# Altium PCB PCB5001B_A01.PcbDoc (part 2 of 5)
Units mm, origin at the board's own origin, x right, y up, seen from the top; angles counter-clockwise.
Board outline 115 x 60 mm, 6 copper layers (Top Layer, GND Layer 2, Signal Layer 3, Signal Layer 4, VCC Layer 5, Bottom Layer), stack 1.555 mm thick; 370 components, 274 nets, 1305 pads, 1129 vias.
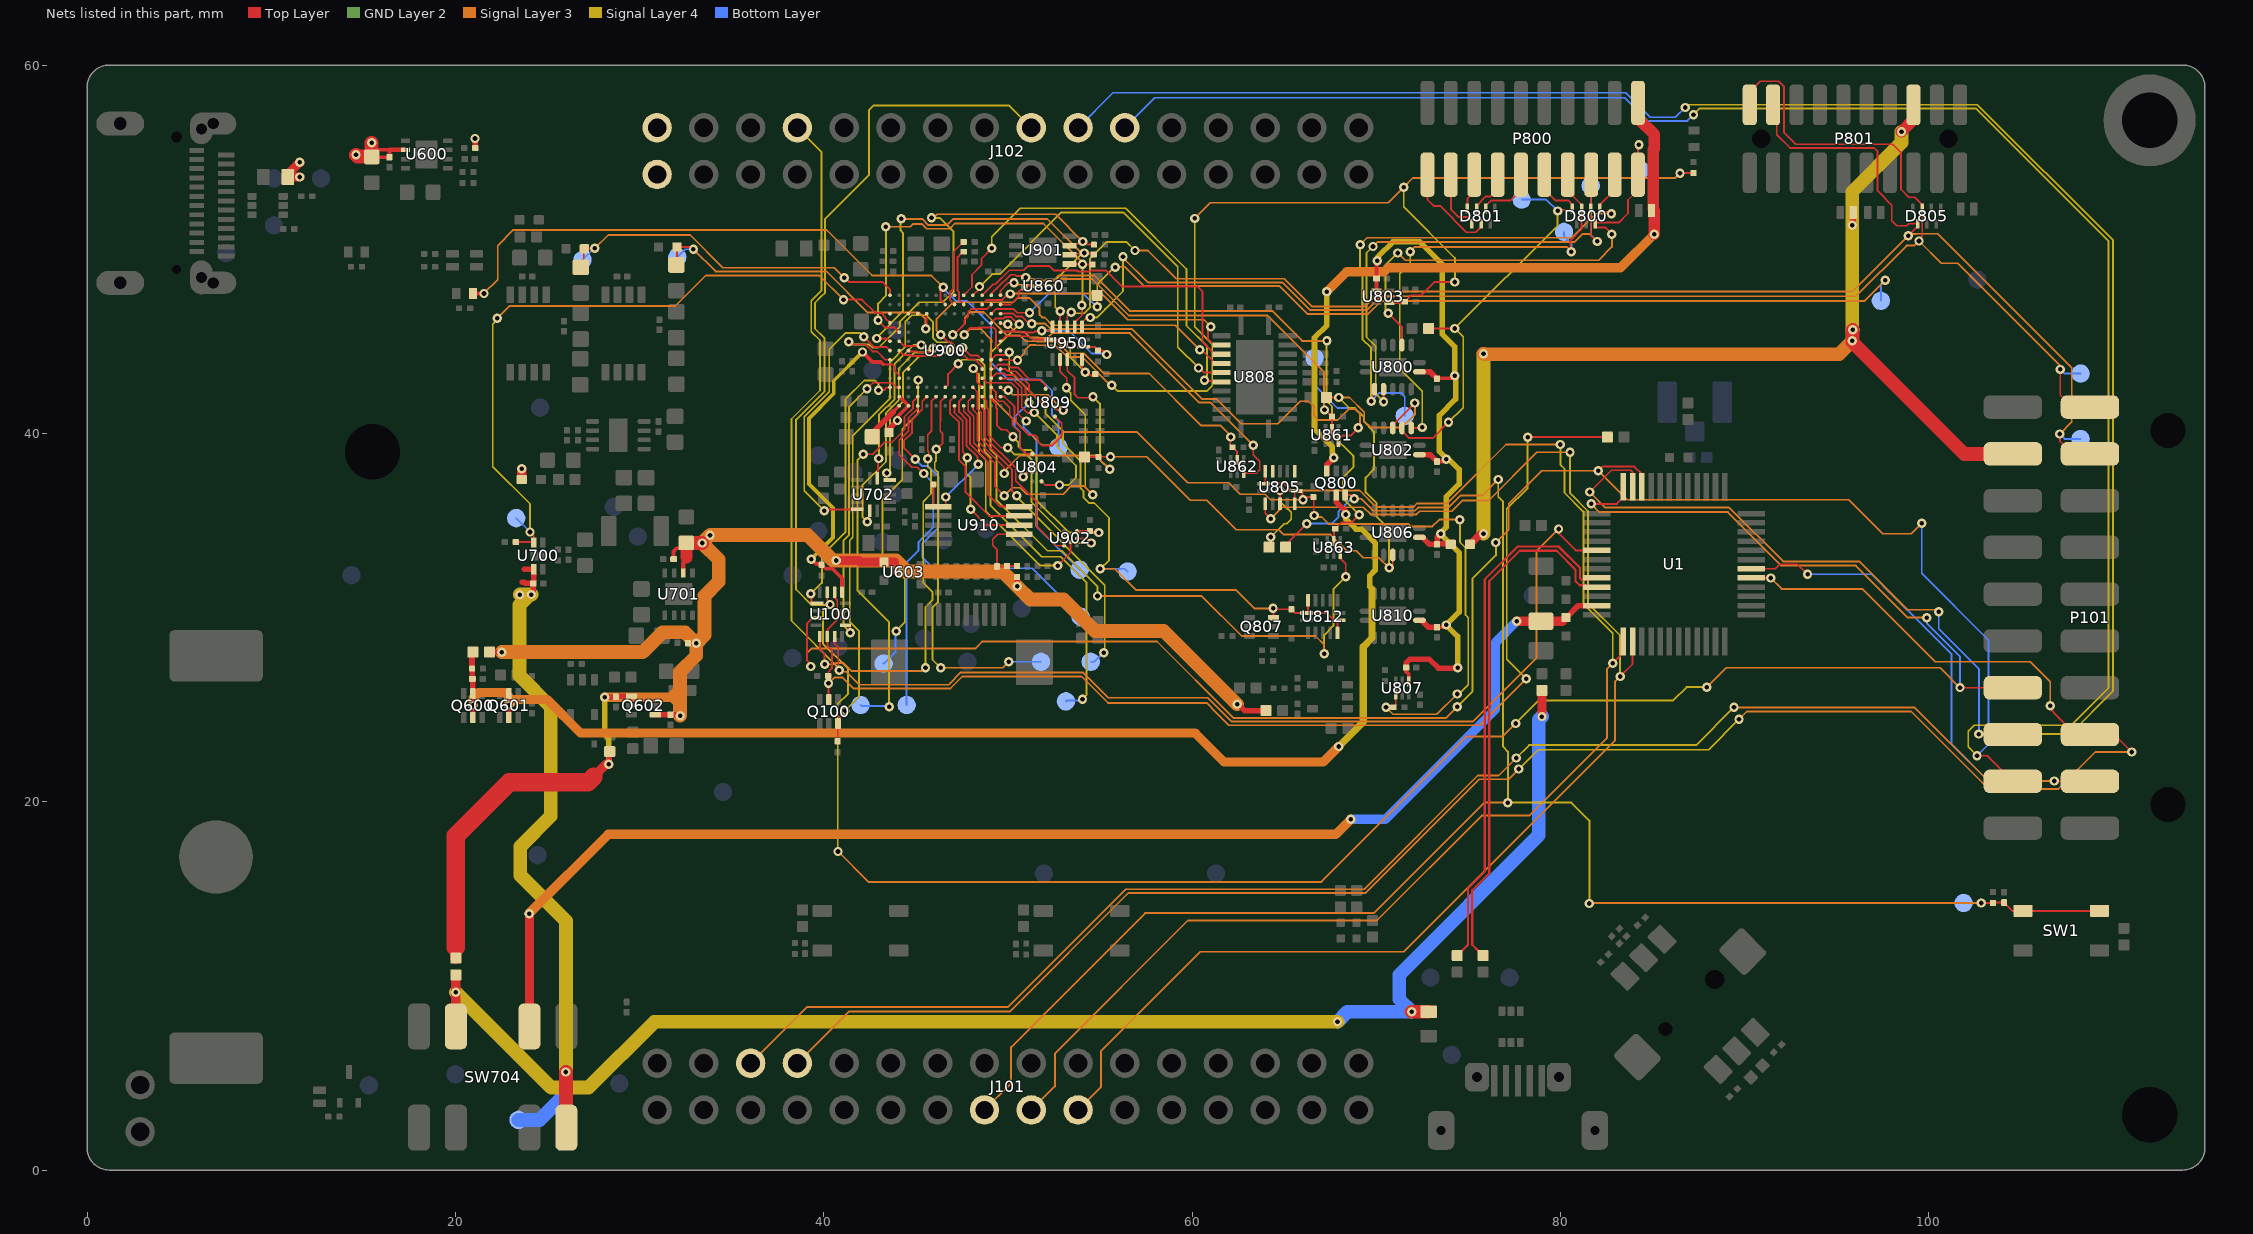
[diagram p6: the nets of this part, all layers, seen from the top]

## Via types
v1: diameter 0.508, hole 0.25, Top Layer to Bottom Layer, tented both sides, 1129 vias

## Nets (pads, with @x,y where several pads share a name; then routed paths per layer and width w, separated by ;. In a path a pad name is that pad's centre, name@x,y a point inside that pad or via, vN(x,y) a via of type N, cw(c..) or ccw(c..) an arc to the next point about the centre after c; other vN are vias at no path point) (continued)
5V: C600.1 C609.1 C611.1 C673.1 C674.1 C702.1 C703.1 C901.1 D806.1 J102.1 J102.2 L600.2 L700.1 L800.1 P101.18 P801.5 Q602.1 Q602.4 R600.2 R622.2 R633.2 R681.2 R690.2 R700.2 R793.2 U600.2 U603.A2 U603.B2 U701.2 U900.A11 U900.B12 | length 163.1
  Top Layer w0.2: C611.1@15.503,55.397 16.417,55.397 C600.1@16.417,55.001 15.726,55.001 C611.1@15.7,54.975 ; C702.1@31.845,33.231 31.845,33.595 32.011,33.761 32.311,33.761 C703.1@32.4,33.85 ; 32.375,32.975 32.475,33.075 ; R700.2@32.627,28.611 32.632,28.606 33.069,28.606 v1(33.075,28.6) ; 43.85,33.025 44.15,32.725 U603.B2@44.15,32.65 44.025,32.65 43.9,32.525 43.9,32.375 44.025,32.25 U603.A2@44.15,32.25 ; v1(44.002,40.702) 44.002,40.902 U900.A11@44.6,41.5 U900.B12@44.1,42
  Top Layer w0.25: 16.417,55.397 U600.2@17.282,55.397 ; U701.2@32.375,32.425 32.375,32.975
  Top Layer w0.3: v1(21.061,56.017) 21.072,56.007 21.072,55.507 R600.2@21.082,55.497 ; R622.2@21.85,28.125 v1(22.525,28.125) ; v1(28.1,25.675) 28.111,25.686 28.703,25.686 C674.1@28.713,25.697 ; v1(28.335,22.042) 28.357,22.065 28.357,22.699 R681.2@28.38,22.722 ; C674.1@28.713,25.697 28.713,25.715 28.723,25.725 Q602.1@29.55,25.725 ; Q602.4@30.85,24.725 C673.1@31.675,24.725 ; C673.1@31.675,24.721 31.685,24.711 32.105,24.711 32.145,24.671 v1(32.201,24.671) ; C901.1@43.55,40.05 43.55,40.25 v1(44.002,40.702) ; v1(50.5,31.7) R633.2@50.5,32.2 ; v1(62.447,25.294) 62.503,25.294 62.853,24.944 R690.2@64.021,24.944 ; v1(95.85,51.3) 95.9,51.35 D806.1@95.9,52
  Top Layer w0.4: L800.1@75.099,33.978 75.671,34.55 v1(75.825,34.55)
  Top Layer w0.5: L600.2@10.9,53.926 v1@11.549,53.926 ; L600.2@10.9,53.926 10.985,54.011 10.985,54.154 11.551,54.719 v1(11.551,54.722) ; L700.1@23.6,37.5 v1(23.6,38.075) ; v1(40.682,33.1) 41.919,33.1 41.994,33.025 C609.1@43.275,33.025 43.85,33.025
  Top Layer w0.508: 27.5,21.35 28.192,22.042 v1(28.335,22.042)
  Top Layer w0.635: R793.2@20.025,11.503 20.025,12.1 ; v1(98.525,56.375) 99.175,57.025 P801.5@99.175,57.841
  Top Layer w0.65: 32.55,33.25 C703.1@32.55,34.047
  Top Layer w0.75: v1(14.6,55.125) 14.686,55.039 15.44,55.039 C611.1@15.45,55.029 ; v1(15.45,55.775) C611.1@15.45,55.029 ; C611.1@15.465,55.014 C611.1@15.45,55.029 ; C703.1@32.55,34.047 32.547,34.05 v1(33.4,34.05) ; v1(95.875,45.625) 95.875,45.05 v1(95.85,45.025) 95.85,44.975 101.935,38.89 P101.18@104.57,38.89
  Top Layer w1: 20.025,12.1 20.025,18.15 22.925,21.05 27.2,21.05 27.5,21.35
  Signal Layer 3 w0.5: v1(28.1,25.675) 31.65,25.675 ; 32.075,26.15 32.075,26.1 31.65,25.675 ; 32.175,25.25 31.75,25.675 ; 32.201,25.675 31.75,25.675 ; 31.65,25.675 31.75,25.675
  Signal Layer 3 w0.75: v1(22.525,28.125) 30.175,28.125 31.25,29.2 32.475,29.2 v1(33.075,28.6) 33.086,28.6 33.525,29.039 33.525,31.175 34.3,31.95 34.3,33.15 v1(33.4,34.05) v1(33.825,34.475) 33.833,34.483 39.117,34.483 40.5,33.1 40.74,33.1 43.925,33.1 44.525,32.5 49.7,32.5 v1(50.5,31.7) 51.218,30.982 53.018,30.982 54.725,29.275 58.466,29.275 61.66,26.081 v1(62.447,25.294) ; v1(32.201,24.671) 32.201,25.675 32.201,27.051 33.075,27.925 v1@33.075,28.525 ; v1(75.825,44.325) 75.85,44.3 95.125,44.3 v1(95.85,45.025) 95.85,45.6 v1(95.875,45.625)
  Signal Layer 4 w0.3: v1(28.1,25.675) 28.1,23.65 28.335,23.415 v1(28.335,22.042)
  Signal Layer 4 w0.75: v1(75.825,34.55) v1(75.825,44.325) ; v1@95.85,45.625 v1(95.85,51.3) 95.85,53.125 98.525,55.8 v1(98.525,56.375)
  other v1: 11.55,53.925
5V_DH_SW: C803.1 C805.1 C809.1 C827.1 C869.1 C870.1 L800.2 U800.14 U802.14 U803.1 U806.14 U807.1 U810.14 | length 42.6
  Top Layer w0.2: C827.1@73.3,29.475 73.675,29.475 v1(73.8,29.6) ; C805.1@73.3,38.475 73.675,38.475 v1(73.8,38.6) ; C803.1@73.325,43 74.15,43 v1(74.275,43.125)
  Top Layer w0.203: U803.1@70.025,47.775 70.019,47.781 C869.1@70.019,48.403 70.019,49.344 v1(70.05,49.375) ; C870.1@71.625,27.284 71.625,27.075 71.763,26.937 U807.1@71.763,26.525
  Top Layer w0.3: C870.1@71.625,27.284 71.625,27.544 71.831,27.75 72.875,27.75 73.375,27.25 74.4,27.25 v1(74.425,27.275) ; U810.14@72.35,29.85 72.475,29.85 72.85,29.475 C827.1@73.3,29.475 ; U806.14@72.35,34.35 72.525,34.35 72.9,33.975 C809.1@73.3,33.975 73.31,33.985 73.31,34.371 73.49,34.551 v1(73.511,34.551) ; U802.14@72.35,38.85 72.925,38.85 C805.1@73.3,38.475 ; U800.14@72.35,43.35 72.925,43.35 C803.1@73.3,42.975 C803.1@73.325,43 ; C809.1@73.31,34 74.028,34 L800.2@74.049,33.978
  Signal Layer 4 w0.203: v1(70.05,49.375) 70.05,49.6 70.08,49.631 70.134,49.631
  Signal Layer 4 w0.3: 70.134,49.631 70.904,50.4 72.375,50.4 73.438,49.337 73.6,49.175 73.6,45.375 74.275,44.7 v1(74.275,43.125) ; v1(73.8,38.6) 73.8,38.656 73.432,39.024 73.432,40.982 74.318,41.868 v1@74.318,42.935 ; v1@73.875,38.675 74.5,38.05 74.5,37.25 73.8,36.55 73.8,34.897 73.511,34.607 73.511,34.514 74.5,33.525 74.5,30.3 v1(73.8,29.6) 74.425,28.975 v1(74.425,27.275)
5V_SENSE: C635.1 R633.1 R634.2 U910.7 | length 4.2
  Top Layer w0.1: R633.1@50.5,32.8 R634.2@49.95,32.8 49.925,32.775 C635.1@49.4,32.775 49.4,33.7 49.182,33.918 49.182,34.263 49.444,34.525 U910.7@50.625,34.525
5V_SW: C610.1 Q600.2 Q600.5 Q601.2 Q601.5 Q800.5 R622.1 R623.2 | length 70.5
  Top Layer w0.3: C610.1@20.925,26.675 20.925,27.2 R623.2@20.9,27.225 20.9,28.075 R622.1@20.95,28.125 ; Q600.2@20.95,24.575 v1(20.95,25.225) 20.95,25.25 Q600.5@20.95,25.875 C610.1@20.95,26.65 ; Q601.2@22.9,24.575 v1(22.9,25.25) Q601.5@22.9,25.875 ; Q800.5@67.825,36.65 67.825,36.275 68.35,35.75 v1(68.35,35.6)
  Signal Layer 3 w0.5: v1(20.95,25.225) 20.95,25.626 21.249,25.925 22.675,25.925 22.9,25.7 v1(22.9,25.25) 23.2,25.55 23.45,25.55 24.975,25.55 26.8,23.725 60.175,23.725 61.75,22.15 67.11,22.15 v1(67.96,23)
  Signal Layer 4 w0.3: v1(68.35,35.6) 68.35,35.35 68.9,34.8 69.2,34.8 69.95,34.05 69.95,32.575 69.643,32.268 69.643,31.682 69.775,31.55
  Signal Layer 4 w0.4: v1(67.96,23) 69.307,24.347 69.307,28.425 69.775,28.893 69.775,31.55
#RESET: R805.2 R809.1 R810.2 U802.4 U806.11 | length 39.3
  Top Layer w0.1: R810.2@54.15,38.725 R809.1@54.925,38.725 54.938,38.737 v1(55.575,38.737) ; R805.2@67.3,41.95 v1(67.975,41.95) ; v1(70.7,32.7) 70.9,32.9 U806.11@70.9,33.4 ; U802.4@70.9,40.3 70.9,40.45 v1(72.1,41.65)
  Signal Layer 3 w0.1: v1(55.575,38.737) 57.537,38.737 59.9,36.375 60.8,36.375 62.407,34.768 64.72,34.768 64.98,34.507 67.518,34.507 68.393,33.632 68.918,33.632 69.3,33.25 70.15,33.25 v1(70.7,32.7) ; v1(67.975,41.95) 68.55,41.95 69.35,41.15 69.35,40.675 69.7,40.325 71.4,40.325 72.1,41.025 v1(72.1,41.65)
  Signal Layer 4 w0.1: v1(67.975,41.95) 68.55,41.375 68.85,41.375 69.325,40.9 69.325,40.65 69.875,40.1 69.875,38.05 69.425,37.6 69.425,36.8 70.025,36.2 70.025,35.475 70.7,34.8 v1(70.7,32.7)
AEM_5V_#ENABLE: U900.L10
AEM_CALIBRATE0: U702.13 U900.G11 | length 13.7
  Top Layer w0.1: v1(42.368,35.213) 42.446,35.291 42.446,35.457 42.5,35.511 U702.13@42.5,35.79 ; U900.G11@44.6,44.5 44.65,44.45 45.099,44.45 45.14,44.409 45.709,44.409 v1(45.935,44.635)
  Signal Layer 4 w0.1: v1(42.368,35.213) 42.1,35.481 42.1,37.189 43.388,38.476 43.388,41.113 44.075,41.8 44.075,43.525 44.95,44.4 45.527,44.4 45.629,44.502 45.803,44.502 v1(45.935,44.635)
AEM_CALIBRATE1: U702.5 U900.G12 | length 12.1
  Top Layer w0.1: v1(43.425,37.85) 43.425,37.525 43.475,37.475 U702.5@43.585,37.475 ; U900.G12@44.1,44.5 44.35,44.25 44.704,44.25 44.752,44.202 46.327,44.202 v1(46.675,44.55)
  GND Layer 2 w0.1: v1(43.425,37.85) v1@43.483,37.908
  Signal Layer 4 w0.1: v1(43.425,37.85) 43.503,37.928 43.6,38.025 43.6,38.75 43.6,41.025 44.3,41.725 44.3,43.3 45.193,44.193 46.318,44.193 v1(46.675,44.55)
AEM_CALIBRATE2: U702.6 U900.H12 | length 9.8
  Top Layer w0.1: U702.6@42.9,37.56 42.947,37.607 42.947,38.592 v1(42.995,38.639) ; U900.H12@44.1,45 44.35,44.75 45.25,44.75 v1(45.302,44.802)
  Signal Layer 4 w0.1: v1(42.995,38.639) 42.995,41.003 43.85,41.858 43.85,43.775 44.877,44.802 v1(45.302,44.802)
AEM_CALIBRATE3: U702.12 U900.G13 | length 15.7
  Top Layer w0.1: v1(40.024,35.799) 40.1,35.875 U702.12@41.815,35.875 ; v1(42.175,45.25) 42.725,44.7 43.4,44.7 U900.G13@43.6,44.5
  Signal Layer 4 w0.1: v1(40.024,35.799) 40.024,35.801 38.946,36.879 38.946,40.914 40.3,42.267 40.3,44.575 41.175,45.45 41.975,45.45 v1(42.175,45.25)
AEM_CURRENT_HIGH_GAIN: C720.1 R764.2 TP706.1 U900.N13 | length 20.5
  Top Layer w0.1: R764.2@26.8,49.025 26.972,49.197 26.972,49.997 C720.1@27,50.025 27.025,50.05 v1(27.575,50.05) ; v1(41.117,48.445) 41.159,48.445 41.38,48.225 43.175,48.225 43.6,47.8 U900.N13@43.6,47.5
  Signal Layer 3 w0.1: v1(27.575,50.05) 28.3,50.775 32.75,50.775 34.525,49 40.563,49 v1(41.117,48.445)
  Bottom Layer w0.1: TP706.1@26.9,49.425 27.525,50.05 v1(27.575,50.05)
AEM_CURRENT_LOW_GAIN: C724.1 R768.2 TP707.1 U900.L9 | length 18.5
  Top Layer w0.1: R768.2@32,49.15 32.025,49.175 C724.1@32.025,50.125 32.8,50.125 v1(32.925,50) ; v1(45.53,45.687) 45.581,45.738 45.581,46.481 U900.L9@45.6,46.5
  Signal Layer 3 w0.1: v1(32.925,50) 34.125,48.8 40.15,48.8 42.375,46.575 45.15,46.575 45.53,46.195 v1(45.53,45.687)
  Bottom Layer w0.1: TP707.1@32.05,49.575 32.475,50 v1(32.925,50)
AEM_SENSE_SELECT: U900.L13
AEM_SWITCH_POS: U900.L11
AEM_VMCU: C708.1 SW704.4 TP709.1 U700.1 | length 39.1
  Top Layer w0.3: 23.625,31.925 23.75,31.925 23.8,31.875 23.851,31.875 23.866,31.86 24.215,31.86 C708.1@24.225,31.85 ; 23.725,32.625 U700.1@24.25,32.625 24.25,31.86 24.24,31.85 C708.1@24.225,31.85 ; v1(24.125,31.25) 24.125,31.306 24.225,31.406 C708.1@24.225,31.85
  Top Layer w0.75: v1(26,5.325) 26,2.325 SW704.4@26.025,2.3
  Signal Layer 4 w0.75: v1(23.491,31.24) 23.501,31.25 v1(24.125,31.25) ; v1@23.984,31.184 23.475,30.675 23.475,26.85 25.175,25.15 25.175,19.216 23.525,17.566 23.525,16 26,13.525 v1(26,5.325)
  Bottom Layer w0.75: TP709.1@23.425,2.725 24.575,2.725 26,4.15 v1(26,5.325)
AEM_VMCU_ENABLE: R763.2 TP715.1 U700.4 U900.K13 | length 38.6
  Top Layer w0.1: R763.2@23.279,34.098 24.227,34.098 U700.4@24.25,34.075 24.25,34.45 v1(24.05,34.65) ; v1(41.075,47.25) 41.092,47.267 42.073,47.267 42.797,46.543 43.113,46.543 43.343,46.313 43.343,46.257 U900.K13@43.6,46
  Signal Layer 3 w0.1: v1(22.275,46.25) 22.95,46.925 31.95,46.925 33.6,48.575 39.75,48.575 v1(41.075,47.25)
  Signal Layer 4 w0.1: v1(22.275,46.25) 22.275,46.179 22.025,45.929 22.025,38.2 24.05,36.175 v1(24.05,34.65)
  Bottom Layer w0.1: TP715.1@23.3,35.4 v1(24.05,34.65)
BC_ADC_SPI_CIPO: U900.B6 U910.9 | length 9.1
  Top Layer w0.1: U900.B6@47.1,42 46.85,41.75 46.85,41.1 47.35,40.6 47.35,38.55 47.7,38.2 47.7,36.8 48.975,35.525 U910.9@50.625,35.525
BC_ADC_SPI_COPI: U900.A6 U910.8 | length 8.8
  Top Layer w0.1: U900.A6@47.1,41.5 47.1,41.133 47.55,40.683 47.55,38.996 47.8,38.746 v1(47.8,38.675) ; v1(47.975,35.875) 48.825,35.025 U910.8@50.625,35.025
  Signal Layer 4 w0.1: v1@47.725,38.5 47.725,37.85 47.975,37.6 v1(47.975,35.875)
BC_ADC_SPI_CS: R982.2 U900.B5 U910.1 | length 8.9
  Top Layer w0.1: R982.2@45.954,37.231 45.954,36.125 46.054,36.025 U910.1@46.225,36.025 46.525,36.025 46.625,36.125 v1(46.625,36.55) ; U900.B5@47.6,42 47.35,41.75 47.35,41.166 47.75,40.766 47.75,39.334 48.355,38.729 48.355,38.37 v1(48.4,38.325)
  Bottom Layer w0.1: v1(46.625,36.55) 48.3,38.225 v1@48.3,38.3
BC_ADC_SPI_SCLK: U900.A5 U910.10 | length 7.3
  Top Layer w0.1: U900.A5@47.6,41.5 47.6,41.199 47.95,40.849 47.95,39.417 48.925,38.442 48.925,36.675 49.575,36.025 U910.10@50.625,36.025
BC_BUTTON_ENABLE: R981.1 U900.H1 U950.6 U950.12 | length 7.2
  Top Layer w0.1: U900.H1@49.6,45 49.88,45.28 50.626,45.28 51.17,45.28 51.35,45.1 U950.6@52.34,45.1 53.024,45.1 53.304,44.82 v1(53.386,44.82) ; U950.12@54.025,44.015 54.025,43.545 54.2,43.37 v1(54.2,43.321) ; v1@54.224,43.346 54.225,43.346 54.28,43.346 54.488,43.138 R981.1@54.653,43.138
  Signal Layer 4 w0.1: v1(53.386,44.82) 53.386,44.136 v1(54.2,43.321)
BC_DAC_OUT: U900.N6
BC_DBG_#RESET: LED903.1 TPJ956.1 U900.M7 | length 43.2
  Top Layer w0.1: v1(46.496,47.942) 46.367,47.942 46.35,47.925 46.35,47.25 U900.M7@46.6,47
  Top Layer w0.2: LED903.1@20.95,47.6 v1(21.55,47.6)
  Signal Layer 3 w0.1: v1(21.55,47.6) 22.3,48.35 22.3,50.2 23.15,51.05 40.15,51.05 42.625,48.575 45.85,48.575 46.49,47.935 v1(46.496,47.942)
  Bottom Layer w0.1: v1(46.496,47.942) 46.496,47.929 46.5,47.925 46.5,47.875 47.175,47.2 47.775,47.2 49.1,45.875 49.1,43.85 50.025,42.925 51.778,42.925 52.4,42.303 52.4,41 52.753,40.647 TPJ956.1@52.753,39.251
BC_DBG_TCK_SWCLK: TPJ954.1 U900.C10 | length 17.7
  Top Layer w0.1: U900.C10@45.1,42.5 45.1,42.775 45.05,42.825 45.05,42.85 45.1,42.9 v1(45.125,42.9) ; v1@45.225,42.852 v1@45.225,42.9
  Signal Layer 4 w0.1: v1(43.943,29.25) 43.943,29.293 44.4,29.75 44.4,32.1 43.2,33.3 43.2,36.425 44.262,37.487 44.262,40.237 45.125,41.1 v1(45.125,42.9)
  Bottom Layer w0.1: TPJ954.1@43.253,27.501 43.9,28.148 43.9,29.207 v1(43.943,29.25)
BC_DBG_TDO_SWO: TPJ955.1 U900.A10 | length 18.2
  Top Layer w0.1: U900.A10@45.1,41.5 45.1,41.342 44.595,40.837 44.595,40.129 44.1,39.634 44.1,38.845 44.783,38.162 45.088,38.162 v1(45.425,37.825)
  Bottom Layer w0.1: TPJ955.1@44.503,25.251 44.503,33.003 45.148,33.648 45.148,34.095 45.304,34.251 45.95,34.897 45.95,37.3 v1(45.425,37.825)
BC_DBG_TMS_SWDIO: TPJ953.1 U900.B10 | length 21
  Top Layer w0.1: v1(42.143,38.872) 42.672,38.872 43.325,39.525 43.708,39.525 44.395,40.212 44.395,40.92 44.85,41.375 44.85,41.75 U900.B10@45.1,42
  Signal Layer 4 w0.1: v1(42.143,38.872) 41.825,38.554 41.825,31.475 43.55,29.75 v1(43.55,25.164)
  Bottom Layer w0.1: TPJ953.1@42.001,25.251 42.045,25.207 43.506,25.207 v1(43.55,25.164)
BC_DISP_AVAILABLE: Q100.6 R142.1 U900.F3 | length 30.6
  Top Layer w0.1: R142.1@40.756,23.283 40.765,23.292 40.765,24.23 Q100.6@40.775,24.24 40.775,24.39 40.89,24.505 40.89,24.628 41.156,24.894 v1(41.156,24.932) ; v1(47.55,44.65) 47.975,44.225 48.375,44.225 U900.F3@48.6,44
  Signal Layer 4 w0.1: v1(41.156,24.932) 41.924,25.7 41.924,29.257 41.412,29.768 41.412,34.187 41.575,34.35 41.575,39.875 43.6,41.9 43.6,43.875 44.425,44.7 44.425,46.075 44.768,46.418 45.564,46.418 45.925,46.057 45.925,45.2 46.173,44.952 46.829,44.952 47.131,44.65 v1(47.55,44.65)
BC_DISP_COM: U900.E11
BC_DISP_PWR_ENABLE: R140.2 U100.13 U900.D12 | length 19.2
  Top Layer w0.1: R140.2@39.888,32.865 R140.2@39.888,32.875 ; 43.185,43.75 43.225,43.75 43.714,43.75 43.85,43.614 43.85,43.604 43.85,43.396 44.1,43.146 U900.D12@44.1,43
  Top Layer w0.2: v1(39.325,33.175) 39.335,33.175 39.596,32.914 39.849,32.914 R140.2@39.888,32.875 ; R140.2@39.888,32.865 39.948,32.805 39.958,32.805 40.114,32.65 40.475,32.65 40.99,32.135 U100.13@40.99,31.375 ; v1(42.106,44.422) 42.652,43.875 43.1,43.875 43.225,43.75
  Signal Layer 4 w0.2: v1(39.325,33.175) 40.5,34.35 40.5,35.95 39.2,37.25 39.2,40.814 40.55,42.164 40.55,42.866 v1(42.106,44.422)
BC_DISP_SPI_COPI: U100.5 U900.B8 | length 22.9
  Top Layer w0.1: U100.5@39.79,28.975 39.79,28.285 40.05,28.025 40.05,27.475 v1(40.048,27.473) ; v1(45.65,38.625) 45.703,38.678 45.703,38.997 45.65,39.05 45.65,39.925 45.85,40.125 45.85,41.75 U900.B8@46.1,42
  Signal Layer 3 w0.1: v1(40.048,27.473) 40.052,27.469 40.593,27.469 40.652,27.528 41.077,27.528 41.501,27.104 45.35,27.104 45.52,27.275 v1(45.525,27.275)
  Signal Layer 4 w0.1: v1(45.525,27.275) 45.525,30.575 45.9,30.95 45.9,31.4 45.4,31.9 45.4,36.3 45.825,36.725 45.825,38.025 45.65,38.2 v1(45.65,38.625)
BC_DISP_SPI_CS: U100.9 U900.C12 | length 16.5
  Top Layer w0.1: U100.9@41.19,29.575 41.382,29.575 41.432,29.525 41.432,29.193 v1(41.444,29.181) ; v1(42.35,42.425) 42.675,42.75 43.704,42.75 43.954,42.5 U900.C12@44.1,42.5
  Signal Layer 4 w0.1: v1(41.444,29.181) 41.075,29.55 41.075,34.2 41.375,34.5 41.375,41.45 v1(42.35,42.425)
BC_DISP_SPI_SCLK: U100.1 U900.C13 | length 15.5
  Top Layer w0.1: v1(39.304,31.286) 39.34,31.25 39.34,30.825 39.39,30.775 U100.1@39.64,30.775 ; v1(42.975,42.35) 43.275,42.35 43.425,42.5 U900.C13@43.6,42.5
  Signal Layer 4 w0.1: v1(39.304,31.286) 39.9,31.883 39.9,33.35 41.175,34.625 41.175,41.844 42.206,42.875 42.8,42.875 42.971,42.704 42.971,42.354 v1(42.975,42.35)
BC_I2C_EXP_ENABLE: R950.1 U900.J1 U950.5 U950.13 | length 8.6
  Top Layer w0.1: U900.J1@49.6,45.5 49.6,45.532 50.656,45.532 50.708,45.48 51.394,45.48 51.444,45.53 51.783,45.53 v1(51.835,45.582) ; v1@51.848,45.598 52.375,45.598 52.425,45.648 U950.5@52.425,45.785 ; U950.13@54.11,44.7 54.71,44.7 54.9,44.51 R950.1@54.9,44.5 55.175,44.5 55.368,44.306 v1(55.368,44.287)
  Bottom Layer w0.1: v1(51.835,45.582) 51.945,45.582 53.318,45.582 54.56,44.34 55.315,44.34 v1(55.368,44.287)
BC_I2C_EXP_SCL: D805.5 P101.17 P801.17 TPJ651.1 U950.3 | length 86
  Top Layer w0.1: U950.3@53.225,45.785 53.225,46.35 v1(53.45,46.575) ; P801.17@91.555,57.841 91.75,57.647 91.75,56.225 92.475,55.5 97.05,55.5 97.225,55.325 97.225,53.175 98,52.4 98,51.55 98.275,51.275 98.8,51.275 98.91,51.385 D805.5@99.4,51.385 99.4,51.25 v1(98.892,50.742) ; v1(107.114,39.967) 107.134,39.947 107.134,39.563 107.808,38.89 P101.17@108.76,38.89
  Signal Layer 3 w0.1: v1(56.902,49.932) 57.603,49.932 59.135,48.4 65,48.4 66.503,46.897 69.406,46.897 70.209,47.7 95.85,47.7 v1(98.892,50.742) 98.97,50.82 99.29,50.82 99.312,50.843 100.497,50.843 107.775,43.565 107.775,40.629 v1(107.114,39.967)
  Signal Layer 4 w0.1: v1(53.45,46.575) 53.5,46.525 54.145,46.525 54.45,46.83 54.45,49.475 55.375,50.4 56.435,50.4 v1@56.902,49.933
  Bottom Layer w0.1: v1(107.114,39.967) 107.381,39.7 TPJ651.1@108.25,39.7
BC_I2C_EXP_SDA: D805.3 P101.19 P801.19 TPJ650.1 U950.1 | length 84
  Top Layer w0.1: U950.1@54.025,45.785 54.025,46.025 54.214,46.214 54.39,46.214 v1(54.468,46.293) ; P801.19@90.285,57.841 90.285,58.565 90.845,59.125 91.858,59.125 92.15,58.833 92.15,56.325 92.775,55.7 98.05,55.7 98.5,55.25 98.5,53.247 98.922,52.825 99.25,52.825 99.605,52.47 99.605,52.26 D805.3@99.65,52.215 99.65,50.713 99.475,50.538 v1(99.475,50.45) ; v1(107.15,43.475) 107.15,42.088 107.808,41.43 P101.19@108.76,41.43
  Signal Layer 3 w0.1: v1(56.25,49.6) 56.25,49.55 57.6,48.2 64.909,48.2 66.414,46.695 69.487,46.695 70.242,47.45 96.05,47.45 98.8,50.2 99.225,50.2 v1(99.475,50.45) 100.687,49.238 101.588,49.238 107.15,43.675 v1(107.15,43.475)
  Signal Layer 4 w0.1: v1(54.468,46.293) 54.818,46.293 55.275,46.75 56.25,47.725 v1(56.25,49.6)
  Bottom Layer w0.1: v1(107.15,43.475) 107.377,43.248 TPJ650.1@108.25,43.248
BC_SPI_CIPO: U900.B3 U902.C3 | length 12.5
  Top Layer w0.1: U900.B3@48.6,42 48.85,41.75 48.85,41.396 48.95,41.296 48.95,39.9 49.625,39.225 v1(50,39.225) ; U902.C3@53.75,34.3 54.275,34.3 v1(54.525,34.05)
  Signal Layer 4 w0.1: v1(50,39.225) 50.375,38.85 51.025,38.85 51.275,38.6 51.275,36.275 53.5,34.05 v1(54.525,34.05)
BC_SPI_COPI: U900.C3 U902.D2 | length 15.9
  Top Layer w0.1: v1(48.125,43.525) 48.325,43.325 48.325,42.775 U900.C3@48.6,42.5 ; v1(52.7,32.825) 53.4,33.525 U902.D2@53.4,34.1
  Signal Layer 4 w0.1: v1(48.125,43.525) 48.425,43.225 48.425,38.95 48.8,38.575 48.8,35.775 51.75,32.825 v1(52.7,32.825)
BC_SPI_CS: R906.1 U900.B2 U902.A3 | length 12.4
  Top Layer w0.1: U900.B2@49.1,42 49.1,41.854 49.35,41.604 49.35,41.396 49.4,41.346 49.4,40.45 49.646,40.204 49.65,40.204 49.71,40.204 49.714,40.2 49.9,40.2 v1(50.275,39.825) ; U902.A3@53.75,34.7 R906.1@54.45,34.7 54.492,34.658 54.895,34.658 v1(54.937,34.617)
  Signal Layer 4 w0.1: v1(50.275,39.825) 50.575,39.525 50.575,39.3 50.775,39.1 51.25,39.1 51.55,38.8 51.55,36.375 53.3,34.625 53.308,34.617 v1(54.937,34.617)
BC_SPI_SCLK: U900.A3 U902.E1 | length 9.7
  Top Layer w0.1: U900.A3@48.6,41.5 48.6,41.364 48.75,41.214 48.75,39.8 50.425,38.125 50.425,37.431 51.55,36.306 51.55,34.975 52.625,33.9 U902.E1@53.05,33.9
BC_TRACECLK: TPJ957.1 U900.B7 | length 21
  Top Layer w0.1: v1(46.108,39.148) 46.148,39.148 46.443,39.443 46.443,40.007 46.325,40.125 46.325,40.658 46.35,40.692 46.35,41.75 U900.B7@46.6,42
  Signal Layer 3 w0.1: v1(46.35,27.275) 49.731,27.275 v1(50.053,27.597)
  Signal Layer 4 w0.1: v1(46.108,39.148) 46.105,39.145 46.105,38.511 46.032,38.438 46.032,38.068 46.2,37.9 46.2,30.825 45.9,30.525 45.9,27.725 v1(46.35,27.275)
  Bottom Layer w0.1: v1(50.053,27.597) 50.051,27.599 TPJ957.1@51.799,27.599
BC_TRACED0: TPJ958.1 U900.C7 | length 25.3
  Top Layer w0.1: U900.C7@46.6,42.5 46.75,42.65 46.75,43.225 v1(47.3,43.775)
  Signal Layer 4 w0.1: v1(47.3,43.775) 47.525,44 48.45,44 48.725,43.725 48.725,39.025 49.05,38.7 49.05,36.1 51.85,33.3 52.875,33.3 54.275,31.9 54.275,25.819 54.05,25.594 v1(54.05,25.556)
  Bottom Layer w0.1: TPJ958.1@53.15,25.45 53.203,25.503 53.997,25.503 v1(54.05,25.556)
BC_TRACED1: TPJ959.1 U900.C4 | length 18.3
  Top Layer w0.1: U900.C4@48.1,42.5 48.35,42.25 48.35,41.331 48.55,41.131 48.55,39.7 50.225,38.025 50.225,36.875 v1(50.475,36.625)
  Signal Layer 4 w0.1: v1(50.475,36.625) 50.475,36.55 55.262,31.763 55.262,28.162 55.199,28.099 v1(55.212,28.086)
  Bottom Layer w0.1: TPJ959.1@54.499,27.599 54.699,27.599 55.125,28.025 55.186,28.086 v1(55.212,28.086)
BC_TRACED2: TPJ960.1 U900.D3 | length 13.5
  Top Layer w0.1: U900.D3@48.6,43 48.85,42.75 50.192,42.75 50.55,42.392 50.55,41.075 50.95,40.675 v1(51,40.675)
  Bottom Layer w0.1: v1(51,40.675) 50.85,40.525 50.85,40.35 51.55,39.65 51.55,34.947 TPJ960.1@53.899,32.598
BC_TRACED3: TPJ961.1 U900.B9 | length 20.5
  Top Layer w0.1: v1@45.003,38.578 44.35,39.231 44.35,39.601 44.795,40.047 44.795,40.754 45.35,41.309 45.35,41.75 U900.B9@45.6,42
  Bottom Layer w0.1: v1(44.978,38.603) 45.356,38.225 45.675,38.225 46.225,37.675 46.225,34.889 45.348,34.012 45.348,33.277 45.95,32.675 51.325,32.675 TPJ961.1@53.95,30.05
BC_UIF_BUTTON0: U900.B4 U950.9 | length 19.9
  Top Layer w0.1: U900.B4@48.1,42 47.85,41.75 47.85,41.231 48.15,40.931 48.15,39.5 49.3,38.35 49.3,37.125 v1(49.8,36.625) ; U950.9@52.825,44.015 52.825,43.375 53.197,43.003 53.197,42.499 v1(53.18,42.482)
  Signal Layer 3 w0.1: v1(49.8,36.625) 50.225,37.05 50.675,37.05 51.025,36.7 53,36.7 53.45,37.15 54.125,37.15 v1(54.6,36.675)
  Signal Layer 4 w0.1: v1(53.18,42.482) 53.18,42.411 53.416,42.174 53.416,41.809 54.2,41.025 54.2,37.075 v1(54.6,36.675)
BC_UIF_BUTTON1: U900.A4 U950.10 | length 18.5
  Top Layer w0.1: U900.A4@48.1,41.5 48.1,41.298 48.35,41.048 48.35,39.6 49.8,38.15 v1(49.8,37.825) ; U950.10@53.225,44.015 53.225,43.409 53.619,43.015 53.619,42.121 53.804,41.936 54.561,41.936 v1(54.621,41.996)
  Signal Layer 3 w0.1: v1@49.85,37.725 49.85,38 50.65,38.8 54.775,38.8 v1(55.525,38.05)
  Signal Layer 4 w0.1: v1(54.621,41.996) 55,41.617 55,38.575 v1(55.525,38.05)
BC_VCOM_CTS: U863.3 U900.K2 | length 40
  Top Layer w0.1: U900.K2@49.1,46 49.35,46.25 49.769,46.25 49.837,46.318 50.186,46.318 50.579,45.925 v1(50.625,45.925) ; U863.3@68.05,33.45 68.05,33.225 68.35,32.925 v1(68.35,32.225)
  Signal Layer 3 w0.1: v1(54.869,31.17) 60.53,31.17 62.7,29 66.706,29 67.175,28.531 v1(67.175,28.043)
  Signal Layer 4 w0.1: v1(50.625,45.925) 49.05,44.35 49.05,39.15 49.375,38.825 49.375,36.4 52.15,33.625 52.925,33.625 54.875,31.675 54.875,31.176 v1(54.869,31.17) ; v1(67.175,28.043) 67.175,29.05 67.675,29.55 67.675,31.55 v1(68.35,32.225)
BC_VCOM_CTS_DIR: R853.2 U863.5 U900.N2 | length 33.4
  Top Layer w0.1: U900.N2@49.1,47.5 49.1,47.575 49.4,47.875 50.144,48.619 50.381,48.619 50.452,48.548 50.895,48.548 v1(50.973,48.47) ; U863.5@67.7,34.15 67.7,34.75 R853.2@67.775,34.825 68.125,35.175 68.675,35.175 v1(69.075,35.575)
  Signal Layer 3 w0.1: v1(50.973,48.47) 51.051,48.392 51.361,48.392 51.45,48.303 52.478,48.303 52.757,48.582 54.678,48.582 56.61,46.65 64.35,46.65 65.975,45.025 v1(67.325,45.025)
  Signal Layer 4 w0.1: v1(67.325,45.025) 67.3,45 67.3,41.767 67.6,41.467 67.6,39.925 68.743,38.782 68.775,38.75 68.775,38.2 68.2,37.625 68.2,36.45 v1(69.075,35.575)
BC_VCOM_ENABLE: Q807.3 R840.1 TP930.1 U812.5 U812.6 U812.12 U812.13 U900.F2 | length 33.2
  Top Layer w0.1: U900.F2@49.1,44 49.35,44.25 49.8,44.25 49.95,44.4 v1(50.075,44.4) ; v1(64.4,30.5) v1@64.425,30.475 ; Q807.3@64.55,30 Q807.3@64.425,30 v1@64.425,30.475 ; U812.12@66.3,30.935 66.3,30.335 U812.13@66.215,30.25 ; U812.5@67.9,29.165 U812.6@67.9,29.85 ; U812.6@67.985,29.85 U812.6@67.9,29.85 ; v1@64.425,30.475 64.45,30.45 R840.1@65.4,30.45 65.6,30.25 U812.13@66.215,30.25 ; U812.13@66.215,30.25 67.325,30.25 67.725,29.85 U812.6@67.9,29.85
  Signal Layer 3 w0.1: v1(55.018,32.65) 55.8,32.65 56.95,31.5 62.375,31.5 63.375,30.5 v1(64.4,30.5)
  Signal Layer 4 w0.1: v1(50.075,44.4) 50.075,43.4 52.05,41.425 52.05,41.075 53,40.125 53,39.45 53.95,38.5 53.95,37.025 54.1,36.875 54.1,36.525 54.4,36.225 54.675,36.225 55.493,35.407 55.493,33.125 v1(55.018,32.65)
  Bottom Layer w0.1: v1(55.018,32.65) 56.35,32.65 TP930.1@56.5,32.5
BC_VCOM_RTS: U862.3 U900.K1 | length 19.1
  Top Layer w0.1: U900.K1@49.6,46 49.675,45.925 v1(50,45.925) ; U862.3@62.8,37.85 63.499,37.85 63.676,38.027 63.676,38.494 63.324,38.847 v1(63.324,39.367)
  Signal Layer 3 w0.1: v1(50,45.925) 50.4,45.525 50.899,45.525 51.218,45.206 51.655,45.206 51.672,45.189 52.139,45.189 52.4,45.45 55.225,45.45 56.625,45.45 60.4,41.675 61.016,41.675 v1(63.324,39.367)
BC_VCOM_RTS_DIR: R852.2 U862.5 U900.M2 | length 23.1
  Top Layer w0.1: v1(47,45.35) 47.056,45.35 47.64,45.935 47.64,46.14 47.85,46.35 47.85,46.604 47.996,46.75 48.85,46.75 U900.M2@49.1,47 ; v1(62.105,39.808) 62.075,39.778 62.075,39.375 R852.2@62.2,39.25 62.45,39 U862.5@62.45,38.55
  Signal Layer 3 w0.1: v1(47,45.35) 47.056,45.35 47.675,45.969 47.675,46.3 47.975,46.6 48.675,46.6 49.95,45.325 50.65,45.325 50.969,45.006 51.572,45.006 51.589,44.989 52.661,44.989 53.3,44.35 54.124,44.35 55.066,43.408 55.211,43.263 57.662,43.263 60.5,40.425 61.556,40.425 62.105,39.876 v1(62.105,39.808)
BC_VCOM_RXD: R882.2 TPJ606.1 U900.L2 | length 54.8
  Top Layer w0.1: U900.L2@49.1,46.5 49.35,46.75 50.319,46.75 50.512,46.557 51.168,46.557 v1(51.175,46.55) ; v1(54.843,46.874) 54.843,47.493 R882.2@54.85,47.5
  Signal Layer 3 w0.1: v1(55.826,49.024) 55.851,49.05 56.35,49.05 57.4,48 64.756,48 66.262,46.494 69.569,46.494 70.261,47.186 96.511,47.186 v1(97.65,48.325)
  Signal Layer 4 w0.1: v1(54.843,46.874) 54.85,46.88 54.85,48.1 55.774,49.024 v1(55.826,49.024)
  Bottom Layer w0.1: v1(51.175,46.55) 52.221,47.596 54.104,47.596 54.826,46.874 v1(54.843,46.874) ; TPJ606.1@97.404,47.202 97.404,48.079 v1(97.65,48.325)
BC_VCOM_RXD_DIR: R850.2 U860.5 U900.M1 | length 2.6
  Top Layer w0.1: U900.M1@49.6,47 49.75,47 50.156,47 50.568,47.412 50.568,47.668 50.722,47.822 50.79,47.822 50.9,47.932 R850.2@50.9,47.942 50.957,48 U860.5@51.6,48
BC_VCOM_TXD: TPJ607.1 U861.3 U900.L1 | length 31.4
  Top Layer w0.1: U900.L1@49.6,46.5 49.618,46.518 50.269,46.518 50.429,46.357 50.762,46.357 51.244,45.875 51.3,45.931 v1(51.3,45.95) ; U861.3@67.95,39.55 67.95,39.675 68.158,39.882 68.607,39.882 v1(69.025,40.3)
  Signal Layer 3 w0.1: v1(51.3,45.95) 51.303,45.953 51.491,45.953 51.513,45.975 52.014,45.975 52.314,45.675 54.85,45.675 56.725,45.675 60.525,41.875 61.325,41.875 62.675,40.525 64.65,40.525 65.875,41.75 66.325,41.75 66.625,41.45 66.625,40.95 66.85,40.725 67.9,40.725 68.5,41.325 68.875,41.325 69.125,41.075 69.125,40.4 v1(69.025,40.3)
  Bottom Layer w0.1: TPJ607.1@66.653,44.101 66.653,42.622 67.9,41.375 68.825,41.375 69.125,41.075 69.125,40.4 v1(69.025,40.3)
BC_VCOM_TXD_DIR: R851.2 U861.5 U900.N1 | length 23.5
  Top Layer w0.1: U900.N1@49.6,47.5 49.6,47.75 50.023,48.173 50.223,48.173 v1(50.333,48.173) ; v1(67.193,41.275) 67.227,41.275 67.59,40.912 R851.2@67.6,40.912 U861.5@67.6,40.25
  Signal Layer 3 w0.1: v1(50.333,48.173) 50.411,48.095 50.591,48.095 50.61,48.077 52.535,48.077 52.84,48.382 53.859,48.382 54.595,48.382 56.577,46.4 64.1,46.4 67.175,43.325 67.175,41.293 v1(67.193,41.275)
BOARD_ID_SCL: R907.2 U900.H13 U901.6 U950.4 | length 25.2
  Top Layer w0.1: v1(42.875,45.157) 42.882,45.15 43.45,45.15 U900.H13@43.6,45 ; U950.4@52.825,45.785 52.83,45.79 52.83,46.622 v1(52.836,46.627) ; U901.6@53.345,49.7 53.401,49.756 54.106,49.756 v1(54.15,49.8) 54.181,49.769 54.621,49.769 R907.2@54.665,49.726
  Signal Layer 3 w0.1: v1(44.2,51.65) 45.351,51.65 45.687,51.314 46.689,51.314 47.025,51.65 52.125,51.65 53.975,49.8 v1(54.15,49.8)
  Signal Layer 4 w0.1: v1(42.875,45.157) 42.875,45.2 44.3,46.625 44.3,50.9 44.175,51.025 44.175,51.625 v1(44.2,51.65) ; v1(52.836,46.627) 52.806,46.627 52.575,46.858 52.575,48.312 54.063,49.8 v1(54.15,49.8)
BOARD_ID_SDA: R908.2 U900.J12 U901.5 U950.2 | length 23.4
  Top Layer w0.1: v1(42.95,46.15) 43.35,45.75 43.85,45.75 U900.J12@44.1,45.5 ; U901.5@53.345,49.2 53.349,49.196 54.049,49.196 54.065,49.18 54.587,49.18 R908.2@54.598,49.168 ; U950.2@53.625,45.785 53.625,46.025 54.025,46.425 54.025,46.95 v1(54.02,46.955)
  Signal Layer 3 w0.1: v1(43.375,51.225) 43.944,51.225 44.406,51.225 44.694,51.225 44.837,51.368 45.351,51.368 45.604,51.114 46.839,51.114 47.125,51.4 51.925,51.4 54.054,49.271 v1(54.054,49.191)
  Signal Layer 4 w0.1: v1(42.95,46.15) 42.95,47.05 43.375,47.475 v1(43.375,51.225) ; v1(54.02,46.955) 54.054,46.99 v1(54.054,49.191)
BOARD_ID_WP: R909.2 U900.F13 U901.7 | length 25.2
  Top Layer w0.1: v1(41.35,44.975) 41.46,44.975 41.61,44.825 42.275,44.825 42.65,44.45 42.9,44.45 43.35,44 U900.F13@43.6,44 ; U901.7@53.345,50.2 53.445,50.3 53.84,50.3 53.96,50.421 v1(54.071,50.421) ; v1@54.071,50.41 54.191,50.41 v1@54.259,50.342 ; v1@54.175,50.3 54.217,50.342 v1@54.259,50.342 ; R909.2@54.676,50.251 54.351,50.251 v1@54.259,50.342
  Signal Layer 3 w0.1: v1(45.85,51.707) 45.96,51.707 46.153,51.9 52.591,51.9 v1(54.071,50.421)
  Signal Layer 4 w0.1: v1(41.35,44.975) 41.46,44.975 41.61,44.825 42.475,44.825 42.65,44.65 42.975,44.65 44.15,45.825 44.15,46.083 45.192,47.125 46.475,47.125 47.05,47.7 47.05,50.95 46.293,51.707 v1(45.85,51.707)
BOARD_VER0: R930.1 U900.M5 | length 3.2
  Top Layer w0.1: U900.M5@47.6,47 47.35,47.25 47.35,47.675 47.268,47.757 47.268,49.571 47.45,49.753 47.492,49.753 R930.1@47.602,49.863
BOARD_VER1: R931.1 U900.M6 | length 3.8
  Top Layer w0.1: U900.M6@47.1,47 46.85,47.25 46.85,47.675 47.068,47.893 47.068,49.878 47.59,50.4 R931.1@47.6,50.4
DBG_VREGO: C902.1 U900.A12 | length 2.4
  Top Layer w0.1: C902.1@42.55,39.875 42.6,39.825 C902.1@42.625,39.825
  Top Layer w0.2: 43.778,41.178 U900.A12@44.1,41.5
  Top Layer w0.3: C902.1@42.625,39.825 42.625,40.025 43.778,41.178
DEBUG_#RESET_C2CKPS: C8.1 J101.15 Q800.6 R9.2 R302.2 SW1.1 SW1.2 TP154.1 | length 106.8
  Top Layer w0.1: R302.2@65.075,33.825 65.301,34.051 65.301,34.176 v1(66.225,35.1) ; Q800.6@68.325,36.65 68.6,36.65 v1(68.8,36.45) ; v1(102.85,14.5) R9.2@103.5,14.5 103.525,14.525 C8.1@104.1,14.525 104.55,14.075 SW1.2@109.075,14.075
  Signal Layer 3 w0.1: J101.15@48.73,3.262 50.175,4.707 50.175,6.675 57.45,13.95 69.875,13.95 75.875,19.95 v1(77.15,19.95) ; v1(68.8,36.45) 69.2,36.45 69.85,35.8 72.098,35.8 72.273,35.975 73.925,35.975 74.575,36.625 75.75,36.625 v1(76.625,37.5) ; v1(81.575,14.475) 81.6,14.5 v1(102.85,14.5)
  Signal Layer 4 w0.1: v1(76.625,37.5) 76.625,36.568 76.893,36.3 76.893,22.982 77.15,22.725 v1(77.15,19.95) 80.6,19.95 81.575,18.975 v1(81.575,14.475) ; v1(102.85,14.5) v1@102.85,14.685
  Bottom Layer w0.1: v1(66.225,35.1) 67.575,35.1 67.957,35.482 67.957,35.763 68.644,36.45 v1(68.8,36.45) ; TP154.1@101.9,14.5 v1(102.85,14.5)
DEBUG_#RESET_IN: U808.7 U900.N5 | length 23.9
  Top Layer w0.1: U900.N5@47.6,47.5 48.05,47.95 48.05,48.133 48.054,48.136 48.054,48.462 48.05,48.465 48.05,48.625 48.575,49.15 48.575,49.5 v1(49.125,50.05) ; v1(60.676,42.885) 60.719,42.842 61.563,42.842 U808.7@61.605,42.8
  Signal Layer 4 w0.1: v1(49.125,50.05) 49.125,50.675 50.675,52.225 56.4,52.225 59.7,48.925 59.7,45.85 60.817,44.733 60.817,43.136 60.676,42.995 v1(60.676,42.885)
DEBUG_DH_SW_ENABLE: R817.2 R900.1 U803.4 U900.F1 | length 61
  Top Layer w0.1: U900.F1@49.6,44 50.05,44 50.075,43.975 50.522,43.975 v1(50.523,43.977) ; U803.4@70.725,47.075 71.475,47.075 R817.2@71.55,47.15 71.9,47.5 72.45,47.5 73.175,48.225 v1(74.275,48.225) ; v1(86.5,54.125) 86.515,54.14 R900.1@87.235,54.14
  Signal Layer 3 w0.1: v1(50.523,43.977) 50.919,44.373 50.919,44.514 51.211,44.806 51.489,44.806 51.506,44.789 52.578,44.789 53.217,44.15 54.041,44.15 v1@55.591,42.6 ; v1(60.15,51.675) 61,52.525 70.65,52.525 v1(71.5,53.375) 72,53.875 84.458,53.875 86.25,53.875 v1(86.5,54.125)
  Signal Layer 4 w0.1: v1(55.646,42.625) 55.971,42.3 60.81,42.3 61.1,42.59 61.1,44.85 60.15,45.8 v1(60.15,51.675) ; v1(71.5,53.375) 71.5,52.3 74.275,49.525 v1(74.275,48.225)
DEBUG_MCU_SW_ENABLE: R814.2 R815.2 U805.5 U805.6 U805.12 U805.13 U807.4 U900.G1 | length 57.9
  Top Layer w0.1: v1(47.625,45.35) 47.625,45.4 47.957,45.732 48.388,45.732 48.406,45.75 49.225,45.75 49.35,45.625 49.35,44.75 U900.G1@49.6,44.5 ; U805.12@63.975,37.955 63.975,37.355 U805.13@63.89,37.27 64.47,37.27 64.525,37.325 64.95,37.325 65.405,36.87 U805.6@65.66,36.87 ; U805.5@65.575,36.185 65.575,36.785 U805.6@65.66,36.87 ; v1(66.642,35.543) 66.608,35.577 66.608,36.525 R815.2@66.59,36.542 66.278,36.542 66.135,36.4 v1(66.025,36.4) 66.005,36.42 66.005,36.745 65.95,36.8 65.95,36.82 65.9,36.87 U805.6@65.66,36.87 ; v1(70.532,25.13) R814.2@70.932,25.13 71.063,25.261 U807.4@71.063,25.825
  Signal Layer 3 w0.1: v1(47.625,45.35) 47.95,45.675 48.525,45.675 49.075,45.125 49.075,41.994 51.162,39.907 51.312,39.907 51.632,39.587 51.862,39.357 52.31,39.357 53.028,40.075 57.025,40.075 59.775,37.325 62,37.325 62.625,36.7 63.961,36.7 64.261,36.4 v1(66.025,36.4) ; v1(66.642,35.543) 66.719,35.465 67.029,35.465 67.409,35.085 71.753,35.085 71.887,34.95 73.05,34.95 73.422,35.322 v1(74.547,35.322) ; v1(70.532,25.13) 70.912,24.75 73.3,24.75 v1(74.4,25.85)
  Signal Layer 4 w0.1: v1(74.4,25.85) 74.4,25.75 74.995,26.345 74.995,30 74.851,30.144 74.851,33.799 74.547,34.103 v1(74.547,35.322)
DEBUG_RESET_#OE: U804.A1 U900.D1 | length 9.9
  Top Layer w0.1: U900.D1@49.6,43 49.625,42.975 50.25,42.975 50.75,42.475 50.75,41.425 51.075,41.1 51.25,41.1 51.375,41.225 51.381,41.225 51.416,41.19 51.436,41.169 v1(51.436,41.139) ; U804.A1@51.825,37.4 52.025,37.2 v1(52.8,37.2)
  Signal Layer 4 w0.1: v1(51.436,41.139) 52.675,39.9 52.675,39.281 53.7,38.256 53.7,37.6 53.3,37.2 v1(52.8,37.2)
DEBUG_TCK_SWCLK_#OE: U809.A1 U900.B1 | length 6.4
  Top Layer w0.1: U900.B1@49.6,42 49.817,42 50.35,41.467 50.35,40.975 50.457,40.868 50.457,40.612 50.463,40.607 50.463,40.587 51.15,39.9 51.5,39.9 51.625,39.775 51.625,39.575 51.85,39.35 52.425,39.35 52.925,39.85 52.925,40.55 U809.A1@52.55,40.925
DEBUG_TCK_SWCLK_C2CK: J101.17 R302.1 U1.13 U805.3 | length 80.8
  Top Layer w0.1: R302.1@64.175,33.825 64.275,33.925 v1(64.275,34.375) ; U805.3@64.775,36.185 v1@64.775,36.75 ; v1@82.85,27.525 83.425,28.1 U1.13@83.425,28.7
  Signal Layer 3 w0.1: J101.17@51.27,3.262 52.55,4.542 52.55,6.325 59.775,13.55 70.042,13.55 75.742,19.25 78.322,19.25 82.525,23.453 82.525,27.206 82.844,27.525 82.847,27.525 v1(82.847,27.528) ; v1@64.825,36.9 69.1,36.9 70,36 72.015,36 72.215,36.2 73.85,36.2 77.05,39.4 v1(80,39.4)
  Signal Layer 4 w0.1: v1(64.275,34.375) 64.998,35.098 65.138,35.098 65.385,35.345 65.385,35.485 65.385,35.715 64.775,36.325 v1(64.775,36.9) ; v1(80,39.4) 80,38.3 80.225,38.075 80.225,36.781 81.25,35.756 81.25,30.742 82.85,29.142 v1@82.85,27.528
DEBUG_TCK_SWCLK_IN: U808.4 U900.N3 | length 17.3
  Top Layer w0.1: U900.N3@48.6,47.5 49.2,48.1 49.325,48.1 50.086,48.861 50.727,48.861 50.728,48.863 50.863,48.863 51.1,49.1 52.25,49.1 52.495,48.855 53.732,48.855 53.789,48.798 54.471,48.798 54.523,48.85 55.319,48.85 56.199,47.97 60.308,47.97 60.575,47.703 60.575,44.95 61.225,44.3 U808.4@61.605,44.3
DEBUG_TCK_SWCLK_OUT: U809.B1 U900.C1 | length 4.5
  Top Layer w0.1: U900.C1@49.6,42.5 49.75,42.35 v1(50.025,42.35) v1@50.05,42.325 ; U809.B1@52.55,41.425 52.713,41.263 v1(53,41.263)
  Signal Layer 3 w0.1: v1(50.025,42.35) 50.275,42.1 52.163,42.1 v1(53,41.263)
DEBUG_TDI_#OE: U809.B2 U900.E1 | length 3.5
  Top Layer w0.1: U900.E1@49.6,43.5 49.858,43.5 49.983,43.375 50.433,43.375 51.153,42.655 51.153,42.322 U809.B2@52.05,41.425
DEBUG_TDI_C2DPS: U805.11
DEBUG_TDI_IN: U808.6 U900.N4 | length 21.6
  Top Layer w0.1: U900.N4@48.1,47.5 48.461,47.861 v1(48.461,47.975) ; v1(60.354,43.554) 60.416,43.554 60.67,43.3 U808.6@61.605,43.3
  Signal Layer 4 w0.1: v1(48.461,47.975) 49.139,48.653 49.553,48.653 52.9,52 56.275,52 59.225,49.05 59.225,44.683 v1(60.354,43.554)
DEBUG_TDI_OUT: U809.D2 U900.E2 | length 3.7
  Top Layer w0.1: U900.E2@49.1,43.5 49.225,43.5 49.475,43.75 49.975,43.75 50.143,43.582 50.524,43.582 51.209,42.898 51.762,42.898 52.05,42.61 U809.D2@52.05,42.425
DEBUG_TDO_SWO: U805.8
DEBUG_TDO_SWO_IN: U808.5 U900.E3 | length 21.9
  Top Layer w0.1: v1(46.35,45.35) 46.75,44.95 46.92,44.95 47.085,44.785 47.085,44.465 47.325,44.225 47.645,44.225 47.845,44.025 48.2,44.025 48.6,43.625 U900.E3@48.6,43.5 ; v1(60.424,44.537) 60.513,44.537 61.25,43.8 U808.5@61.605,43.8
  Signal Layer 3 w0.1: v1(46.35,45.35) 46.125,45.575 46.125,46.225 47.025,47.125 50.294,47.125 50.519,47.35 51.183,47.35 51.725,46.808 51.725,46.434 51.859,46.3 51.987,46.3 52.412,45.875 54.767,45.875 59.086,45.875 v1(60.424,44.537)
DEBUG_TMS_SWDIO_#OE: U804.B2 U900.D2 | length 8.8
  Top Layer w0.1: U900.D2@49.1,43 49.35,43.25 49.825,43.25 49.9,43.175 50.35,43.175 50.953,42.572 50.953,42.23 51.025,42.158 51.025,41.8 v1(51.15,41.675) ; v1@50.775,37.65 51.025,37.9 U804.B2@51.325,37.9
  Bottom Layer w0.1: v1(50.825,37.65) 51.275,38.1 51.275,38.625 50.675,39.225 50.675,40.075 50.35,40.4 50.35,40.875 v1(51.15,41.675)
DEBUG_TMS_SWDIO_C2D: J101.19 U1.14 U805.1 | length 76.7
  Top Layer w0.1: U805.1@63.975,36.185 63.975,35.675 v1(64.275,35.375) ; v1(83.247,26.803) 83.925,27.481 U1.14@83.925,28.7
  Signal Layer 3 w0.1: J101.19@53.81,3.262 55.05,4.502 55.05,6.45 60.45,11.85 71.487,11.85 82.975,23.338 82.975,26.531 v1(83.247,26.803) ; v1(64.275,35.375) 64.893,35.993 69.307,35.993 69.7,35.6 72.181,35.6 72.356,35.775 74.1,35.775 74.675,36.35 76.1,36.35 78.725,38.975 80.519,38.975 v1(80.522,38.978)
  Signal Layer 4 w0.1: v1(80.522,38.978) 80.522,36.767 81.5,35.789 81.5,30.775 83.247,29.028 v1(83.247,26.803)
DEBUG_TMS_SWDIO_IN: U808.3 U900.M3 | length 15
  Top Layer w0.1: U900.M3@48.6,47 48.85,47.25 49.704,47.25 50.029,47.575 v1(50.125,47.575) ; v1(61.025,45.8) 60.875,45.65 60.875,45.125 61.2,44.8 U808.3@61.605,44.8
  Signal Layer 3 w0.1: v1(50.125,47.575) 50.146,47.596 55.098,47.596 56.519,46.175 60.65,46.175 v1(61.025,45.8)
DEBUG_TMS_SWDIO_OUT: U804.D2 U900.C2 | length 4.9
  Top Layer w0.1: U900.C2@49.1,42.5 49.35,42.25 49.35,41.9 49.35,41.896 49.496,41.75 49.748,41.75 50.1,41.398 50.1,40.925 50.25,40.775 50.25,40.45 50.675,40.025 50.675,39.225 51,38.9 U804.D2@51.325,38.9
DEBUG_TRACECLK: D801.2 P800.12 | length 3.2
  Top Layer w0.1: D801.2@75.95,52.215 75.95,52.35 76.25,52.65 77.3,52.65 77.865,53.215 P800.12@77.865,54.05
DEBUG_TRACED0: D801.3 P800.14 | length 2.5
  Top Layer w0.1: D801.3@75.45,52.215 75.45,52.375 75.95,52.875 76.225,52.875 76.595,53.245 P800.14@76.595,54.05
DEBUG_TRACED1: D801.4 P800.16 | length 2
  Top Layer w0.1: D801.4@74.95,52.215 74.95,52.75 75.325,53.125 P800.16@75.325,54.05
DEBUG_TRACED2: D801.5 P800.18 | length 3.4
  Top Layer w0.1: P800.18@74.055,54.05 74.055,52.17 74.475,51.75 75,51.75 75.2,51.55 D801.5@75.2,51.385
DEBUG_TRACED3: D801.6 P800.20 | length 5.3
  Top Layer w0.1: P800.20@72.785,54.05 72.785,52.7 73.127,52.358 73.467,52.358 74.9,50.925 75.4,50.925 75.7,51.225 D801.6@75.7,51.385
DH_#RESET: D800.4 P800.10 R816.1 TPJ811.1 U802.3 | length 24.8
  Top Layer w0.1: U802.3@71.4,40.3 71.4,40.15 71.8,39.75 73.075,39.75 v1(73.925,40.6) ; R816.1@72.85,45.7 v1@74.175,45.7 ; P800.10@79.135,54.05 79.135,53.24 79.725,52.65 80.425,52.65 80.65,52.425 D800.4@80.65,52.215 80.585,52.15 79.918,52.15 v1(79.85,52.082)
  Signal Layer 4 w0.1: v1(73.925,40.6) 74.725,41.4 74.725,45.25 v1(74.275,45.7) 79.85,51.275 v1(79.85,52.082)
  Bottom Layer w0.1: TPJ811.1@77.9,52.7 79.232,52.7 v1(79.85,52.082)
DH_TCK_SWCLK: D800.1 P800.4 TPJ818.1 U800.9 | length 30
  Top Layer w0.1: v1(69.725,41.75) 69.725,41.95 69.9,42.125 U800.9@69.9,42.4 ; v1(82.775,51.925) 82.681,52.019 82.195,52.019 82.15,52.064 82.15,52.425 82.945,53.22 P800.4@82.945,54.05
  Signal Layer 3 w0.1: v1(69.125,50.25) 69.5,50.625 80.625,50.625 81.925,51.925 v1(82.775,51.925)
  Signal Layer 4 w0.1: v1(69.125,50.25) 69.118,50.243 69.118,49.032 69.25,48.9 69.25,45.125 69.725,44.65 v1(69.725,41.75)
  Bottom Layer w0.1: v1(69.725,41.75) 70.175,42.2 71.35,42.2 71.55,42 TPJ818.1@71.55,40.95
DH_TDI: D800.3 P800.8 TPJ820.1 U802.2 | length 25.9
  Top Layer w0.1: U802.2@71.9,40.3 72.475,40.3 v1(72.5,40.325) ; P800.8@80.405,54.05 80.405,53.17 81.15,52.425 81.15,51.074 80.55,50.474 80.55,49.924 v1(80.599,49.875)
  Signal Layer 3 w0.1: v1(71.85,49.875) 72.1,50.125 80.349,50.125 v1(80.599,49.875)
  Signal Layer 4 w0.1: v1(71.85,49.875) 71.85,49.25 71.282,48.682 71.282,43.518 72.5,42.3 v1(72.5,40.325)
  Bottom Layer w0.1: TPJ820.1@80.2,50.95 80.2,50.706 80.603,50.303 80.603,49.879 v1(80.599,49.875)
DH_TDO_SWO: D800.2 P800.6 TPJ812.1 U800.10 | length 29.1
  Top Layer w0.1: v1@70.4,41.825 U800.10@70.4,42.4 ; P800.6@81.675,54.05 81.65,54.025 81.65,50.775 v1(82,50.425)
  Signal Layer 3 w0.1: v1(69.825,50.15) 70.075,50.4 80.775,50.4 81.2,50.825 81.6,50.825 v1(82,50.425)
  Signal Layer 4 w0.1: v1(69.825,50.15) 69.475,49.8 69.475,45.225 69.975,44.725 69.975,42.15 v1(70.4,41.725)
  Bottom Layer w0.1: TPJ812.1@81.65,53.45 81.65,50.775 v1(82,50.425)
DH_TMS_SWDIO: D800.7 P800.2 TPJ814.1 U800.3 | length 27.1
  Top Layer w0.1: v1(70.663,46.527) 71.4,45.79 U800.3@71.4,44.8 ; v1(82.8,50.825) 82.436,51.189 81.945,51.189 81.9,51.234 81.9,51.445 83.17,51.445 83.675,51.95 83.675,52.675 84.215,53.215 P800.2@84.215,54.05 84.221,54.056 84.221,55.628 v1(84.268,55.675)
  Signal Layer 3 w0.1: v1(71.175,49.8) 71.574,49.401 82.076,49.401 82.8,50.125 v1(82.8,50.825)
  Signal Layer 4 w0.1: v1(70.663,46.527) 70.496,46.693 70.496,49.121 v1(71.175,49.8)
  Bottom Layer w0.1: v1(84.268,55.675) 84.229,55.636 84.229,54.429 84.225,54.425 TPJ814.1@84.35,54.3
DH_VTREF: D809.1 P800.1 Q800.3 | length 37.2
  Top Layer w0.3: Q800.3@67.325,37.95 67.325,38.3 v1(67.7,38.675)
  Top Layer w0.635: P800.1@84.215,57.95 84.268,57.897 84.268,57.068 85.1,56.235 85.1,55.459 85.04,55.399 85.04,52.16 85.1,52.1 v1(85.1,50.825)
  Signal Layer 3 w0.5: v1(67.318,47.702) 68.398,48.782 70.43,48.782 70.644,48.996 83.271,48.996 v1(85.1,50.825)
  Signal Layer 4 w0.3: v1(67.318,47.702) 67.318,45.868 66.65,45.2 66.65,40.25 67.61,39.29 67.61,38.912 67.66,38.862 67.66,38.715 v1(67.7,38.675)
  Bottom Layer w0.5: v1(67.318,47.702) v1(67.318,47.702)
DISP_CS: J102.8 U1.5 U100.7 | length 85.3
  Top Layer w0.1: U100.7@40.59,28.975 40.59,28.579 40.79,28.379 40.79,27.191 v1(40.845,27.135) ; v1(79.904,34.812) 79.904,34.571 80.825,33.65 U1.5@81.975,33.65
  Signal Layer 3 w0.1: v1(40.845,27.135) 40.923,27.057 41.234,27.057 41.934,26.357 46.784,26.357 47.452,27.025 54.075,27.025 55.45,25.65 60.85,25.65 62.15,24.35 75.25,24.35 78.7,27.8 78.7,33.609 v1(79.904,34.812)
  Signal Layer 4 w0.1: J102.8@38.57,56.602 39.875,55.297 39.875,47.75 39.325,47.2 39.325,45.532 39.799,45.059 39.799,42.332 38.25,40.783 38.25,29.827 40.845,27.232 v1(40.845,27.135)
DISP_ENABLE: Q100.2 R141.2 R301.2 U100.6 U100.14 | length 65.4
  Top Layer w0.1: Q100.2@40.286,25.529 40.246,25.569 40.258,25.581 v1(40.258,26.425) 40.258,26.816 R141.2@40.242,26.832 40.244,26.834 40.244,27.039 40.443,27.237 40.443,28.232 40.2,28.475 40.2,28.965 U100.6@40.19,28.975 40.208,28.993 40.208,29.358 40.737,29.887 40.737,30.93 40.59,31.077 U100.14@40.59,31.375 ; v1(78.225,39.8) R301.2@82.55,39.8
  Signal Layer 3 w0.1: v1(40.258,26.425) 40.576,26.743 41.025,26.743 41.61,26.157 46.884,26.157 47.527,26.8 54,26.8 55.437,25.363 60.787,25.363 61.342,24.808 62,24.15 75.625,24.15 v1(78.15,26.675)
  Signal Layer 4 w0.1: v1(78.15,26.675) 77.093,27.732 77.093,35.9 78.225,37.032 v1(78.225,39.8)
DISP_SCLK: J102.18 P101.8 U1.48 U100.15 | length 152.3
  Top Layer w0.1: U100.15@40.19,31.375 40.19,30.956 40.344,30.802 v1(40.344,30.709) ; v1(81.672,36.172) 83.072,36.172 83.425,36.525 U1.48@83.425,37.1 ; v1(101.7,26.2) 101.71,26.19 P101.8@104.57,26.19
  Signal Layer 3 w0.1: v1(40.775,17.3) 42.428,15.647 67.024,15.647 74.926,23.55 76.875,23.55 v1(77.575,24.25) ; v1(81.672,36.172) 82.119,35.725 89.1,35.725 92,32.825 96.05,32.825 98.875,30 v1(99.9,30) ; v1(87.95,26.225) 89,27.275 100.625,27.275 v1(101.7,26.2)
  Signal Layer 4 w0.1: v1@40.313,30.678 39.347,30.678 38.5,31.525 38.5,40.75 40.05,42.3 40.05,45.164 39.525,45.689 39.525,47.1 39.837,47.412 40.075,47.65 40.075,51.65 42.45,54.025 42.45,57.55 42.7,57.8 50.072,57.8 J102.18@51.27,56.602 ; v1(40.344,30.709) 39.951,30.316 39.951,28.585 41.325,27.211 41.325,25.875 40.763,25.313 40.763,17.312 v1(40.775,17.3) ; v1(77.575,24.25) 78.825,25.5 86.131,25.5 86.856,26.225 v1(87.95,26.225)
  Bottom Layer w0.1: v1(99.9,30) 99.9,29.7 101.7,27.9 v1(101.7,26.2)
DISP_SI: J102.22 P101.4 U1.46 U100.3 | length 190.9
  Top Layer w0.1: 39.24,29.825 39.1,29.685 39.1,27.656 39.304,27.452 v1(39.304,27.342) ; 39.24,29.825 39.39,29.975 U100.3@39.59,29.975 ; v1(82.05,37.975) 82.275,38.2 84.025,38.2 84.425,37.8 U1.46@84.425,37.1 ; v1(102.625,22.5) 103.18,22.5 P101.4@104.57,21.11
  Signal Layer 3 w0.1: v1(39.304,27.342) 39.304,27.452 39.1,27.656 39.1,28.088 39.33,28.318 48.218,28.318 48.6,28.7 58.098,28.7 62.248,24.55 73.8,24.55 v1(74.4,25.15) ; v1(76.5,34.075) 77.2,34.775 77.2,36.192 78.983,37.975 v1(82.05,37.975) 83.625,36.4 95.65,36.4 97.5,34.55 99.05,34.55 v1(99.625,35.125)
  Signal Layer 4 w0.1: v1(74.4,25.15) 75.225,25.975 75.225,32.1 76.5,33.375 v1(76.5,34.075) ; v1(87.229,57.296) 87.225,57.3 87.575,57.65 102.55,57.65 109.775,50.425 109.775,26.183 107.742,24.15 102.475,24.15 102.15,23.825 102.15,22.975 v1(102.625,22.5)
  Bottom Layer w0.1: J102.22@56.35,56.602 57.973,58.225 83.5,58.225 84.756,56.969 86.903,56.969 v1(87.229,57.296) ; v1(99.625,35.125) 99.625,32.4 103.25,28.775 103.25,23.125 v1(102.625,22.5)
EFM_USB_DM: R119.2 U1.9 | length 29.1
  Top Layer w0.12: R119.2@75.8,11.65 R119.2@75.56,11.89 ; U1.9@81.975,31.65 81.45,31.65 81.35,31.75 81.05,31.75 80.825,31.975 80.825,32.6 79.8,33.625 77.79,33.625 76.14,31.975 76.14,16.116 75.22,15.196 75.22,12.23 ; 75.22,12.23 R119.2@75.56,11.89 ; 75.22,12.23 R119.2@75.56,11.89
EFM_USB_DP: R118.2 U1.8 | length 29.1
  Top Layer w0.12: R118.2@74.4,11.65 R118.2@74.48,11.73 ; R118.2@74.405,11.73 R118.2@74.48,11.73 ; U1.8@81.975,32.15 81.47,32.15 81.37,32.05 81.165,32.05 81.065,32.15 81.065,32.699 79.899,33.865 77.69,33.865 75.9,32.075 75.9,16.216 74.98,15.296 74.98,12.305 74.98,12.23 R118.2@74.48,11.73
EFM_USB_VBUS: L1.2 R120.2 R793.1 SW704.6 | length 80.4
  Top Layer w0.508: SW704.6@20.025,7.8 v1(20.025,9.65) R793.1@20.025,10.603 ; v1(79,24.625) R120.2@79,26.05
  Top Layer w0.75: v1(71.925,8.6) L1.2@72.85,8.6
  Signal Layer 4 w0.75: v1(20.025,9.65) 25.2,4.475 27.225,4.475 30.8,8.05 v1(67.9,8.05)
  Bottom Layer w0.75: v1(67.9,8.05) 68.45,8.6 v1(71.925,8.6) 71.25,9.275 71.25,10.6 78.825,18.175 78.825,24.45 v1(79,24.625)
EFM_VREGIN: C3.1 C4.1 SW704.7 U1.11 | length 73.2
  Top Layer w0.305: C4.1@80.3,30 80.325,30 80.975,30.65 U1.11@81.966,30.65
  Top Layer w0.508: v1(24,13.925) 24.025,13.9 SW704.7@24.025,7.8 ; v1(77.625,29.8) 80.1,29.8 C4.1@80.3,30
  Signal Layer 3 w0.508: v1(24,13.925) 28.3,18.225 67.8,18.225 v1(68.625,19.05)
  Bottom Layer w0.508: v1(68.625,19.05) 70.5,19.05 76.475,25.025 76.475,28.65 v1(77.625,29.8)
EXP_HEADER3: J101.6 P101.3 U1.30 | length 106.7
  Top Layer w0.1: U1.30@90.375,32.65 91.66,32.65 91.91,32.9 92.875,32.9 v1(93.425,32.35) ; v1(106.825,21.125) 106.84,21.11 P101.3@108.76,21.11
  Signal Layer 3 w0.1: J101.6@36.03,5.802 39.078,8.85 50,8.85 56.4,15.25 69.342,15.25 75.517,21.425 76.65,21.425 v1(77.6,22.375) ; v1(89.428,25.122) 99.228,25.122 103.225,21.125 v1(106.825,21.125)
  Signal Layer 4 w0.1: v1(77.6,22.375) 78.3,23.075 87.378,23.075 v1@89.425,25.122
  Bottom Layer w0.1: v1(93.425,32.35) 96.9,32.35 101.25,28 101.25,23.125 103.25,21.125 v1(106.825,21.125)
EXP_HEADER5: J101.8 P101.5 U1.29 | length 108.4
  Top Layer w0.1: U1.29@90.375,32.15 90.398,32.127 90.422,32.15 v1(91.425,32.15) ; v1(106.6,25.218) 106.6,25.052 106.825,24.827 106.825,24.8 107.975,23.65 P101.5@108.76,23.65 110.075,23.65 v1(111.025,22.7)
  Signal Layer 3 w0.1: J101.8@38.57,5.802 41.368,8.6 50.1,8.6 56.55,15.05 69.425,15.05 75.6,21.225 77.2,21.225 v1(77.75,21.775) ; v1(89.7,24.475) 90.125,24.9 99.05,24.9 103.25,20.7 107.05,20.7 109.05,22.7 v1(111.025,22.7) ; v1(91.425,32.15) 92.018,31.557 96.393,31.557 100.35,27.6 105.525,27.6 106.6,26.525 v1(106.6,25.218)
  Signal Layer 4 w0.1: v1(77.75,21.775) 78.8,22.825 88.05,22.825 v1(89.7,24.475)
EXP_HEADER6: J102.20 P101.6 U1.47 | length 128.3
  Top Layer w0.1: v1(81.596,36.819) 82.777,38 83.825,38 83.925,37.9 U1.47@83.925,37.1 ; v1(102.725,23.675) 104.497,23.675 P101.6@104.521,23.699
  Signal Layer 3 w0.1: v1(81.596,36.819) 82.44,35.975 89.175,35.975 92.1,33.05 96.225,33.05 98.85,30.425 100.439,30.425 v1(100.55,30.314)
  Signal Layer 4 w0.1: v1(86.775,57.7) 86.925,57.85 88.325,57.85 102.65,57.85 110.018,50.482 110.018,26.018 107.675,23.675 v1(102.725,23.675)
  Bottom Layer w0.1: J102.20@53.81,56.602 55.708,58.5 83.55,58.5 84.881,57.169 86.244,57.169 v1(86.775,57.7) ; v1(100.55,30.314) 100.55,29.4 102.725,27.225 v1(102.725,23.675)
